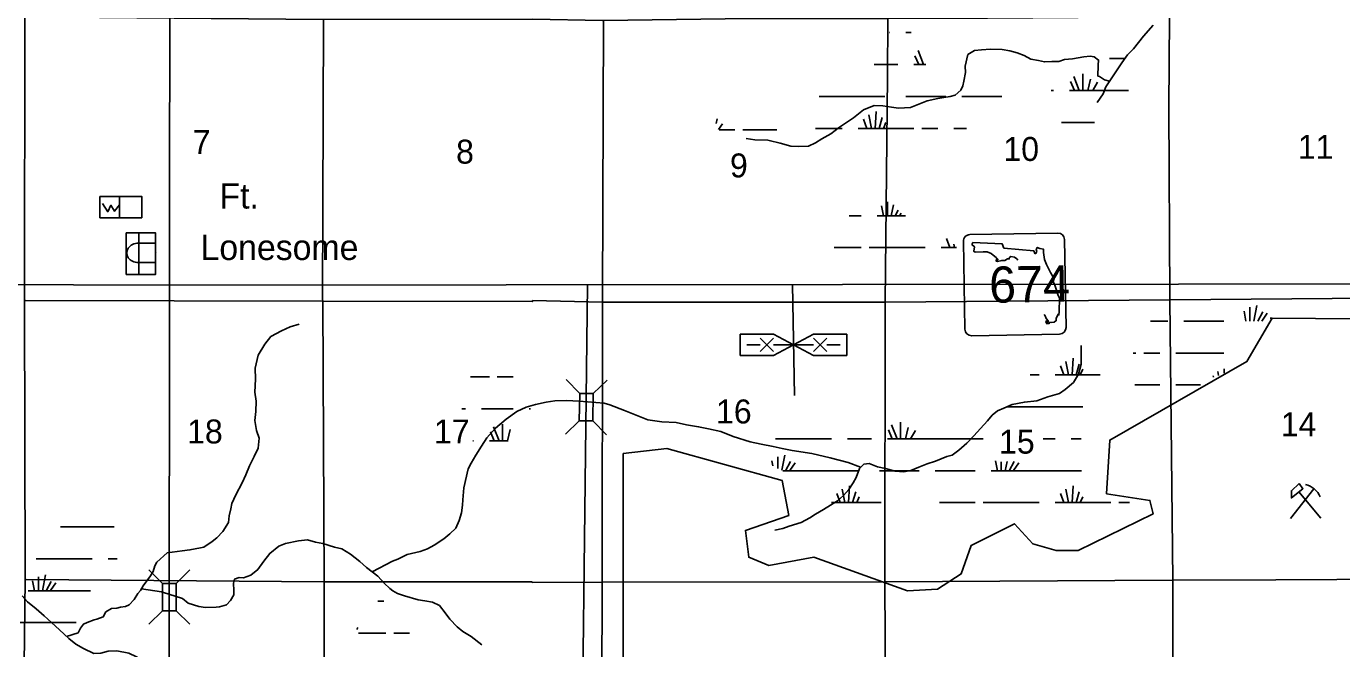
# Model space of a CAD drawing. Extents: x 380424 to 701066, y 1117407 to 1412949.
# Drawn here: x 606273 to 630981, y 1218760 to 1230454 of the extents above; entities that cross this region are included whole.
import ezdxf

# ---------------------------------------------------------------- set-up
doc = ezdxf.new("R2010")
doc.units = 0
for name, color, linetype in [('Bridges', 7, 'Continuous'), ('Bridges and Drawbridges County Highways', 7, 'Continuous'), ('Bridges and Drawbridges Local Roads', 7, 'Continuous'), ('Communities and Subdivisions Names without Post Office', 7, 'Continuous'), ('County Routes Highway Center Lines', 7, 'Continuous'), ('Culture', 7, 'Continuous'), ('Local Roads Paved', 7, 'Continuous'), ('Local Roads Related Cells', 7, 'Continuous'), ('Narrow River Creek and Branch and Slough', 7, 'Continuous'), ('Roadshilelds State Highways', 7, 'Continuous'), ('Section Lines', 7, 'Continuous'), ('Section Numbers', 7, 'Continuous'), ('State Routes Highway Center Lines', 7, 'Continuous'), ('Strip Mining Area', 7, 'Continuous'), ('Swamps', 7, 'Continuous')]:
    doc.layers.add(name, color=color, linetype=linetype)

msp = doc.modelspace()

# ---------------------------------------------------------------- linework, layer by layer
at = {"layer": 'Bridges'}
msp.add_line((616923, 1223552), (617182, 1223805), dxfattribs=at)
at = {"layer": 'Bridges and Drawbridges County Highways'}
for p, q in [((608830, 1219986), (608574, 1220242)), ((609086, 1219986), (609342, 1220242)), ((608830, 1219474), (608574, 1219218)), ((609086, 1219474), (609342, 1219218))]:
    msp.add_line(p, q, dxfattribs=at)
msp.add_lwpolyline([(608830, 1219474), (608830, 1219986), (609086, 1219986), (609086, 1219474)], close=True, dxfattribs=at)
at = {"layer": 'Bridges and Drawbridges Local Roads'}
for p, q in [((616667, 1223556), (616414, 1223815)), ((616660, 1223044), (616401, 1222791)), ((616916, 1223040), (617169, 1222781))]:
    msp.add_line(p, q, dxfattribs=at)
msp.add_lwpolyline([(616923, 1223552), (616916, 1223040), (616660, 1223044), (616667, 1223556)], close=True, dxfattribs=at)
at = {"layer": 'County Routes Highway Center Lines'}
msp.add_lwpolyline([(609082, 1282791), (609001, 1267651), (608943, 1204448), (608786, 1203273)], dxfattribs=at)
at = {"layer": 'Culture'}
for p, q in [((607652, 1226857), (607652, 1227257)), ((607652, 1227257), (608023, 1227257)), ((608023, 1227257), (608023, 1226857)), ((608023, 1226857), (607652, 1226857)), ((608389, 1225793), (608389, 1226573)), ((608380, 1226378), (608700, 1226378)), ((608700, 1226014), (608380, 1226014)), ((608726, 1226196), (608726, 1226196)), ((608726, 1226196), (608726, 1226196)), ((630019, 1221205), (630456, 1221765)), ((630176, 1221706), (630589, 1221213))]:
    msp.add_line(p, q, dxfattribs=at)
for points in [[(608023, 1226857), (608023, 1227257), (608442, 1227257), (608442, 1226857)], [(608151, 1225793), (608151, 1226573), (608700, 1226573), (608700, 1225793)], [(630182, 1221866), (630251, 1221766), (630036, 1221594), (630036, 1221729)]]:
    msp.add_lwpolyline(points, close=True, dxfattribs=at)
msp.add_lwpolyline([(608023, 1227101), (607928, 1226980), (607861, 1227092), (607802, 1226971), (607702, 1227127)], dxfattribs=at)
msp.add_arc((630186, 1221432), 431, 24.5415, 74.8304, dxfattribs=at)
msp.add_ellipse((608380, 1226196), major_axis=(222, 0), ratio=0.821498, start_param=1.570796, end_param=4.712389, dxfattribs=at)
at = {"layer": 'Local Roads Paved'}
for points in [[(616816, 1225597), (616668, 1213393), (616646, 1209630), (616644, 1209324)], [(620664, 1225601), (620701, 1223519)]]:
    msp.add_lwpolyline(points, dxfattribs=at)
at = {"layer": 'Local Roads Related Cells'}
for p, q in [((619684, 1224669), (620309, 1224669)), ((619684, 1224269), (619684, 1224669)), ((620059, 1224344), (620309, 1224594)), ((620309, 1224344), (620059, 1224594)), ((620309, 1224669), (620684, 1224469)), ((620684, 1224469), (621059, 1224669)), ((621059, 1224669), (621684, 1224669)), ((621309, 1224346), (621059, 1224596)), ((621059, 1224344), (621309, 1224594)), ((621684, 1224669), (621684, 1224269)), ((620059, 1224469), (619809, 1224469)), ((620684, 1224469), (620309, 1224269)), ((621059, 1224469), (620309, 1224469)), ((621059, 1224269), (620684, 1224469)), ((621559, 1224469), (621309, 1224469)), ((620309, 1224269), (619684, 1224269)), ((621684, 1224269), (621059, 1224269))]:
    msp.add_line(p, q, dxfattribs=at)
at = {"layer": 'Narrow River Creek and Branch and Slough'}
for points in [[(627438, 1230475), (627260, 1230270), (627070, 1230033), (626960, 1229918), (626849, 1229765), (626723, 1229581), (626550, 1229318), (626497, 1229187), (626387, 1229024)], [(626618, 1229422), (626523, 1229450), (626429, 1229508), (626403, 1229518), (626408, 1229723), (626413, 1229818), (626334, 1229881), (626255, 1229891), (626140, 1229881), (625924, 1229844), (625772, 1229828), (625667, 1229792), (625535, 1229792), (625398, 1229786), (625283, 1229813), (625141, 1229834), (625015, 1229907), (624883, 1229955), (624746, 1229991), (624604, 1230018), (624384, 1230023), (624215, 1230012), (624084, 1230002), (623958, 1229923), (623911, 1229702), (623916, 1229587), (623884, 1229424), (623863, 1229334), (623826, 1229255), (623721, 1229161), (623627, 1229134), (623506, 1229119), (623395, 1229098), (623195, 1229055), (623101, 1229019), (622880, 1228929), (622654, 1228914), (622523, 1228935), (622360, 1228961), (622197, 1228966), (621997, 1228882), (621813, 1228735), (621697, 1228661), (621550, 1228556), (621382, 1228435), (621213, 1228340), (621098, 1228262), (620966, 1228199), (620777, 1228193), (620635, 1228204), (620430, 1228256), (620225, 1228309), (620199, 1228314), (619957, 1228319), (619794, 1228346)], [(607030, 1218989), (607244, 1219056), (607260, 1219082), (607292, 1219145), (607344, 1219219), (607418, 1219255), (607549, 1219303), (607597, 1219313), (607717, 1219361), (607765, 1219450), (607870, 1219518), (607975, 1219524), (608043, 1219539), (608133, 1219555), (608206, 1219581), (608301, 1219687), (608369, 1219797), (608417, 1219855), (608469, 1219939), (608553, 1220060), (608606, 1220128), (608653, 1220212), (608685, 1220317), (608722, 1220387), (608920, 1220562), (609200, 1220601), (609347, 1220617), (609542, 1220654), (609610, 1220670), (609763, 1220775), (609852, 1220843), (609962, 1220964), (610073, 1221132), (610083, 1221259), (610115, 1221385), (610131, 1221485), (610210, 1221653), (610330, 1221874), (610394, 1222026), (610467, 1222194), (610551, 1222373), (610625, 1222526), (610646, 1222715), (610599, 1222862), (610567, 1223046), (610583, 1223214), (610588, 1223409), (610567, 1223582), (610578, 1223824), (610572, 1224029), (610625, 1224276), (610751, 1224481), (610867, 1224623), (611066, 1224734), (611229, 1224807), (611398, 1224855)], [(620335, 1220987), (620483, 1221017), (620604, 1221059), (620830, 1221132), (620993, 1221217), (621098, 1221290), (621245, 1221374), (621376, 1221458), (621513, 1221537), (621624, 1221637), (621723, 1221748), (621802, 1221874), (621860, 1221979), (621923, 1222147), (622002, 1222226), (622107, 1222242), (622260, 1222179), (622412, 1222147), (622591, 1222095), (622754, 1222084), (622885, 1222110), (623038, 1222173), (623195, 1222231), (623348, 1222284), (623564, 1222368), (623663, 1222394), (623790, 1222489), (623942, 1222620), (624068, 1222762), (624194, 1222894), (624326, 1223041), (624415, 1223146), (624515, 1223230), (624636, 1223277), (624789, 1223346), (625020, 1223393), (625251, 1223414), (625461, 1223493), (625677, 1223556), (625787, 1223630), (625940, 1223761), (626035, 1223919), (626087, 1224103), (626087, 1224287), (626087, 1224455)], [(612767, 1220207), (613148, 1220407), (613254, 1220444), (613427, 1220528), (613669, 1220586), (613806, 1220638), (613932, 1220707), (614116, 1220822), (614226, 1220917), (614342, 1221027), (614405, 1221169), (614447, 1221311), (614463, 1221458), (614473, 1221558), (614494, 1221784), (614573, 1222137), (614631, 1222247), (614715, 1222394), (614820, 1222568), (614925, 1222720), (615088, 1222904), (615288, 1223072), (615488, 1223214), (615662, 1223298), (615840, 1223351), (616040, 1223393), (616203, 1223414), (616421, 1223426), (616657, 1223410), (617130, 1223370), (617234, 1223343), (617512, 1223235), (617728, 1223146), (617949, 1223062), (618211, 1223025), (618480, 1223009), (618674, 1222967), (618900, 1222930), (619089, 1222888), (619321, 1222841), (619552, 1222746), (619868, 1222647), (620073, 1222605), (620304, 1222557), (620472, 1222520), (620656, 1222484), (621029, 1222426), (621371, 1222347), (621713, 1222258), (621945, 1222169)], [(614827, 1218835), (614631, 1218987), (614473, 1219082), (614363, 1219171), (614226, 1219313), (614142, 1219434), (614032, 1219571), (613900, 1219634), (613758, 1219660), (613632, 1219676), (613375, 1219750), (613248, 1219797), (613159, 1219850), (613101, 1219892), (612996, 1219991), (612875, 1220123), (612665, 1220286), (612539, 1220396), (612365, 1220533), (612202, 1220638), (612060, 1220670), (611845, 1220738), (611703, 1220764), (611555, 1220806), (611387, 1220785), (611140, 1220738), (611014, 1220685), (610846, 1220549), (610735, 1220402), (610620, 1220249), (610493, 1220144), (610351, 1220091), (610273, 1220097), (610183, 1220065), (610162, 1219991), (610173, 1219855), (610173, 1219771), (610110, 1219666), (610031, 1219587), (609899, 1219545), (609836, 1219539), (609636, 1219534), (609516, 1219555), (609316, 1219618), (609205, 1219702), (608830, 1219824), (608811, 1219828), (608435, 1219884)], [(606193, 1219750), (606293, 1219639), (606456, 1219508), (606608, 1219376), (606745, 1219250), (606897, 1219113), (607071, 1218950), (607202, 1218845), (607344, 1218766), (607544, 1218672), (607670, 1218677), (607812, 1218714), (607970, 1218719), (608196, 1218677), (608343, 1218609), (608454, 1218535), (608580, 1218409), (608599, 1218378)]]:
    msp.add_lwpolyline(points, dxfattribs=at)
at = {"layer": 'Roadshilelds State Highways'}
for p, q in [((625647, 1226570), (623997, 1226541)), ((623874, 1226414), (623903, 1224764)), ((625803, 1224797), (625774, 1226447)), ((624030, 1224641), (625680, 1224670))]:
    msp.add_line(p, q, dxfattribs=at)
for points in [[(624900, 1226058), (624880, 1226083), (624836, 1226118), (624767, 1226127), (624738, 1226113), (624735, 1226083), (624705, 1226086), (624653, 1226055), (624594, 1226054), (624518, 1226033), (624492, 1226039), (624494, 1226082), (624511, 1226053), (624527, 1226070), (624490, 1226112), (624434, 1226154), (624397, 1226183), (624324, 1226215), (624248, 1226217), (624093, 1226211), (624070, 1226227), (624081, 1226313), (624034, 1226355), (624050, 1226395)], [(624050, 1226395), (624605, 1226365), (624636, 1226286), (625200, 1226233), (625214, 1226187), (625238, 1226188), (625253, 1226221), (625243, 1226260), (625262, 1226300), (625312, 1226278), (625378, 1226269), (625379, 1226207), (625401, 1226072), (625436, 1225977), (625508, 1225830), (625555, 1225751), (625582, 1225715), (625563, 1225659), (625591, 1225590), (625625, 1225495), (625650, 1225416), (625677, 1225348), (625679, 1225285), (625674, 1225160), (625672, 1225087), (625670, 1225031), (625656, 1225047), (625641, 1225011), (625618, 1224971), (625619, 1224924), (625580, 1224894), (625537, 1224887), (625501, 1224893), (625488, 1224873), (625445, 1224865), (625425, 1224901), (625434, 1224918), (625448, 1224895), (625465, 1224889), (625464, 1224918), (625427, 1224961), (625413, 1225013), (625390, 1225037)]]:
    msp.add_lwpolyline(points, dxfattribs=at)
for centre, start, end in [((623999, 1226416), 91.0003, 181.0003), ((625649, 1226445), 1.0003, 91.0003), ((625678, 1224795), 271.0003, 1.0003), ((624028, 1224766), 181.0003, 271.0003)]:
    msp.add_arc(centre, 125, start, end, dxfattribs=at)
at = {"layer": 'Section Lines'}
for points in [[(611856, 1230581), (611856, 1230571), (611837, 1225330), (611840, 1225292), (606258, 1225303), (606236, 1225303), (606248, 1230626), (606248, 1230633), (611846, 1230581)], [(617116, 1230564), (617096, 1225358), (617095, 1225270), (615782, 1225299), (615782, 1225285), (615777, 1225285), (611840, 1225292), (611837, 1225330), (611856, 1230571), (611856, 1230581), (615788, 1230586), (615788, 1230591), (617098, 1230564)], [(622455, 1230598), (622446, 1229510), (622408, 1225273), (622396, 1225273), (617095, 1225270), (617096, 1225358), (617116, 1230564), (619399, 1230594)], [(627749, 1230632), (627736, 1228925), (627753, 1225340), (627753, 1225316), (622408, 1225273), (622446, 1229510), (622455, 1230598), (622460, 1230598), (624330, 1230608), (627742, 1230632)], [(633108, 1230669), (633108, 1230651), (633085, 1225417), (633085, 1225359), (627758, 1225316), (627753, 1225316), (627753, 1225340), (627736, 1228925), (627749, 1230632), (629796, 1230666), (633103, 1230669)], [(611840, 1225292), (611868, 1220018), (606271, 1220063), (606252, 1220063), (606252, 1220073), (606236, 1225278), (606236, 1225303), (606258, 1225303)], [(617095, 1225270), (617088, 1220010), (615777, 1220001), (615777, 1220012), (615769, 1220013), (611868, 1220018), (611840, 1225292), (615777, 1225285), (615782, 1225285), (615782, 1225299)], [(622408, 1225273), (622408, 1225265), (622396, 1220013), (617098, 1220010), (617088, 1220010), (617095, 1225270), (622396, 1225273)], [(627753, 1225316), (627808, 1220048), (627801, 1220048), (622401, 1220013), (622396, 1220013), (622408, 1225265), (622408, 1225273)], [(633085, 1225359), (633104, 1223708), (633174, 1220085), (633173, 1220075), (629744, 1220053), (627808, 1220048), (627753, 1225316), (627758, 1225316)], [(611868, 1220018), (611870, 1214702), (611870, 1214647), (608875, 1214632), (606191, 1214649), (606191, 1214707), (606252, 1220063), (606271, 1220063)], [(617088, 1220010), (617087, 1219409), (617051, 1214684), (617028, 1214684), (615772, 1214649), (615772, 1214667), (615764, 1214667), (611870, 1214647), (611870, 1214702), (611868, 1220018), (615769, 1220013), (615777, 1220012), (615777, 1220001)], [(622396, 1220013), (622396, 1220005), (622412, 1217911), (622392, 1214682), (622021, 1214670), (617051, 1214684), (617087, 1219409), (617088, 1220010), (617098, 1220010)], [(627808, 1220048), (627808, 1220040), (627817, 1214726), (626498, 1214703), (622409, 1214683), (622392, 1214682), (622412, 1217911), (622396, 1220005), (622396, 1220013), (622401, 1220013), (627801, 1220048)], [(633173, 1220075), (633194, 1217821), (633225, 1214773), (633225, 1214761), (633210, 1214761), (632047, 1214766), (627817, 1214726), (627808, 1220040), (627808, 1220048), (629744, 1220053)]]:
    msp.add_lwpolyline(points, close=True, dxfattribs=at)
at = {"layer": 'State Routes Highway Center Lines'}
msp.add_lwpolyline([(640551, 1225621), (608969, 1225590), (572811, 1225715), (567889, 1228370), (547875, 1228304), (542500, 1228290), (542132, 1228289), (536228, 1228275), (533934, 1228260), (532069, 1228431), (531223, 1228480), (521382, 1228594), (519319, 1228617), (515590, 1228660)], dxfattribs=at)
at = {"layer": 'Strip Mining Area'}
msp.add_line((629640, 1224973), (629672, 1224971), dxfattribs=at)
for points in [[(629672, 1224971), (629201, 1224154), (626625, 1222678), (626563, 1221672), (627379, 1221546), (627442, 1221295), (626029, 1220604), (625620, 1220604), (625181, 1220729), (624835, 1221106), (624019, 1220698), (623830, 1220164), (623391, 1219881), (622825, 1219849), (621066, 1220478), (620219, 1220321), (619842, 1220478), (619779, 1220981), (620595, 1221264), (620470, 1221923), (618303, 1222520), (617486, 1222426), (617486, 1214728)], [(638922, 1213657), (637963, 1214383), (635074, 1214634), (635011, 1214949), (634351, 1215923), (632938, 1216551), (631368, 1217054), (631996, 1217557), (633692, 1217777), (633880, 1220699), (632436, 1220793), (633880, 1224941), (629640, 1224973)]]:
    msp.add_lwpolyline(points, dxfattribs=at)
at = {"layer": 'Swamps'}
for p, q in [((622196, 1229736), (622646, 1229736)), ((622965, 1229902), (623036, 1229736)), ((625949, 1229511), (626052, 1229249)), ((626118, 1229560), (626118, 1229249)), ((625889, 1229415), (625959, 1229249)), ((626263, 1229463), (626210, 1229249)), ((626396, 1229403), (626306, 1229249)), ((622796, 1229136), (623546, 1229136)), ((623846, 1229136), (624296, 1229136)), ((624296, 1229136), (624596, 1229136)), ((622146, 1228536), (622100, 1228790)), ((622217, 1228536), (622235, 1228852)), ((622294, 1228536), (622352, 1228740)), ((621896, 1228536), (622946, 1228536)), ((622061, 1228536), (621996, 1228708)), ((622371, 1228536), (622420, 1228645)), ((623096, 1228536), (623396, 1228536)), ((622337, 1227082), (622375, 1226896)), ((622446, 1227154), (622446, 1226896)), ((621655, 1226296), (621955, 1226296)), ((622105, 1226296), (623155, 1226296)), ((629146, 1225102), (629183, 1224915)), ((629255, 1225174), (629255, 1224915)), ((629388, 1225210), (629329, 1224916)), ((629497, 1225089), (629403, 1224915)), ((629581, 1225065), (629482, 1224916)), ((628014, 1224915), (628464, 1224915)), ((628464, 1224915), (628764, 1224915)), ((627264, 1224315), (627564, 1224315)), ((627864, 1224315), (628464, 1224315)), ((628464, 1224315), (628764, 1224315)), ((625761, 1223904), (625696, 1224076)), ((625846, 1223904), (625800, 1224159)), ((625917, 1223904), (625934, 1224220)), ((625994, 1223904), (626052, 1224108)), ((615120, 1223866), (615420, 1223866)), ((626070, 1223904), (626119, 1224013)), ((614820, 1223266), (615420, 1223266)), ((614989, 1222832), (615060, 1222666)), ((615049, 1222928), (615152, 1222666)), ((615218, 1222977), (615218, 1222666)), ((622465, 1222870), (622536, 1222704)), ((622525, 1222967), (622628, 1222704)), ((622694, 1223015), (622694, 1222704)), ((622839, 1222919), (622786, 1222704)), ((622972, 1222858), (622882, 1222704)), ((620346, 1222704), (621396, 1222704)), ((621696, 1222704), (622146, 1222704)), ((622446, 1222704), (623796, 1222704)), ((623796, 1222704), (624246, 1222704)), ((625373, 1222704), (625596, 1222704)), ((620628, 1222278), (620534, 1222104)), ((620713, 1222254), (620614, 1222105)), ((622296, 1222104), (623046, 1222104)), ((623346, 1222104), (623796, 1222104)), ((623796, 1222104), (624096, 1222104)), ((624396, 1222104), (626096, 1222104)), ((624478, 1222290), (624515, 1222104)), ((624587, 1222270), (624587, 1222104)), ((624695, 1222276), (624661, 1222104)), ((624828, 1222278), (624734, 1222104)), ((624913, 1222254), (624814, 1222105)), ((621717, 1221504), (621734, 1221820)), ((625917, 1221504), (625934, 1221820)), ((621561, 1221504), (621496, 1221676)), ((621646, 1221504), (621600, 1221759)), ((621794, 1221504), (621852, 1221708)), ((621870, 1221504), (621919, 1221613)), ((625761, 1221504), (625696, 1221676)), ((625846, 1221504), (625800, 1221759)), ((625994, 1221504), (626052, 1221708)), ((626070, 1221504), (626119, 1221613)), ((623796, 1221504), (624096, 1221504)), ((624246, 1221504), (625296, 1221504)), ((625596, 1221504), (626646, 1221504)), ((606460, 1220450), (607510, 1220450)), ((606501, 1220108), (606501, 1219850)), ((606634, 1220145), (606575, 1219850)), ((606392, 1220036), (606429, 1219850)), ((606742, 1220024), (606648, 1219849)), ((606827, 1220000), (606727, 1219851)), ((606160, 1219250), (607210, 1219250)), ((613173, 1219050), (613473, 1219050))]:
    msp.add_line(p, q, dxfattribs=at)
for points in [[(622489, 1230336), (622496, 1230336)], [(622796, 1230336), (622893, 1230336)], [(623025, 1229999), (623128, 1229736)], [(622946, 1229736), (623166, 1229736)], [(626620, 1229849), (626901, 1229849)], [(625522, 1229249), (625570, 1229249)], [(625870, 1229249), (626973, 1229249)], [(621167, 1229136), (622396, 1229136)], [(619229, 1228628), (619247, 1228714)], [(619274, 1228518), (619350, 1228621)], [(619284, 1228508), (619581, 1228508)], [(619731, 1228508), (620370, 1228508)], [(621098, 1228536), (621596, 1228536)], [(623696, 1228536), (623930, 1228536)], [(625720, 1228649), (626339, 1228649)], [(622561, 1227100), (622520, 1226896)], [(622649, 1226998), (622594, 1226895)], [(621730, 1226896), (621955, 1226896)], [(622255, 1226896), (622787, 1226896)], [(622706, 1226945), (622673, 1226896)], [(621446, 1226296), (621655, 1226296)], [(623455, 1226296), (623744, 1226296)], [(623621, 1226296), (623555, 1226468)], [(623706, 1226296), (623694, 1226360)], [(627392, 1224915), (627714, 1224915)], [(627064, 1224315), (627114, 1224315)], [(614618, 1223866), (614970, 1223866)], [(625132, 1223904), (625296, 1223904)], [(625596, 1223904), (626446, 1223904)], [(628575, 1223860), (628564, 1223889)], [(628664, 1223895), (628653, 1223969)], [(628774, 1223936), (628776, 1224019)], [(627098, 1223715), (627564, 1223715)], [(627864, 1223715), (628328, 1223715)], [(624696, 1223304), (626121, 1223304)], [(614456, 1223266), (614520, 1223266)], [(615720, 1223266), (615743, 1223266)], [(615363, 1222880), (615310, 1222666)], [(614663, 1222666), (614670, 1222666)], [(614970, 1222666), (615326, 1222666)], [(625896, 1222704), (626087, 1222704)], [(620387, 1222363), (620387, 1222147)], [(620520, 1222399), (620462, 1222113)], [(620278, 1222290), (620297, 1222194)], [(620480, 1222104), (621896, 1222104)], [(621396, 1221504), (622333, 1221504)], [(623424, 1221504), (623796, 1221504)], [(626796, 1221504), (626993, 1221504)], [(606913, 1221050), (607924, 1221050)], [(607810, 1220450), (607981, 1220450)], [(606310, 1219850), (607477, 1219850)], [(612873, 1219650), (612988, 1219650)], [(612480, 1219121), (612497, 1219159)], [(612512, 1219050), (613023, 1219050)]]:
    msp.add_lwpolyline(points, dxfattribs=at)

# ---------------------------------------------------------------- texts
at = {"layer": 'Communities and Subdivisions Names without Post Office'}
for s, p in [('Ft.', (609900, 1227029)), ('Lonesome', (609545, 1226063))]:
    msp.add_text(s, height=475, rotation=0.0003, dxfattribs=at).set_placement(p)
at = {"layer": 'Roadshilelds State Highways'}
msp.add_text('674', height=680, rotation=1.0003, dxfattribs=at).set_placement((624363, 1225257))
at = {"layer": 'Section Numbers'}
for s, rotation, p in [('7', 0.0003, (609397, 1228053)), ('8', 0.0003, (614345, 1227874)), ('10', 0.0003, (624626, 1227924)), ('11', 0.0003, (630156, 1227964)), ('9', 0.0003, (619490, 1227615)), ('16', 0.0002, (619228, 1222992)), ('18', 0.0003, (609293, 1222616)), ('17', 0.0003, (613930, 1222616)), ('14', 0.0003, (629836, 1222753)), ('15', 0.0003, (624544, 1222425))]:
    msp.add_text(s, height=450, rotation=rotation, dxfattribs=at).set_placement(p)

doc.saveas('drawing.dxf')
